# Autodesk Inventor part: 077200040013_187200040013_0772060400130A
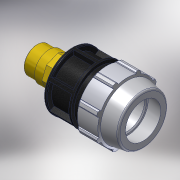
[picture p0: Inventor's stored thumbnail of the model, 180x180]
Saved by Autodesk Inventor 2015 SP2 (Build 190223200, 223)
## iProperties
Created: 2017-02
Part Number: 077200040013_187200040013_0772060400130A
Material: PVC-Piping
Description: PLASSON MALE ADAPTOR INTEGRAL BRASS THREAD 40-1.1/4"
Document SubType Name: Modeling
Designer: KIM
Mass: 92.6774 g
Surface Area: 199.44 cm^2
Volume: 66.1981 cm^3
Density: 1.4 g/cm^3
Appearance: PTFE
Author: KIM
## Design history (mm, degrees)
derived "07720.ipt"
feature "Solid1::07720.ipt"
tag "TaggingFeature1"
body "Solid1"
other parameters: "d4" = 22, "d5" = 22, "d7" = 82, "d8" = 61.5, "d9" = 22, "d11" = 4.4, "d12" = 65.6, "d13" = 120 deg, "d15" = 10 deg, "d16" = 73.8, "d18" = 2, "d19" = 35 deg, "d20" = 17.5 deg, "d21" = 76.26, "d23" = 0, "d25" = 360 deg, "d27" = 1.64, "d34" = 4.1, "d36" = 0, "d42" = 30.8, "d43" = 2.46, "d46" = 1.2, "d49" = 91, "d51" = 154, "d53" = 0.8, "d55" = 360 deg, "d59" = 30.8, "d60" = 41.91, "d61" = 46.101, "d62" = 22, "d63" = 51.33333, "d64" = 29.337, "d65" = 154, "d66" = 16.1482, "d67" = 0, "d68" = 0.8, "d71" = 30 deg, "d72" = 37.719, "E_" = 82, "H_" = 154, "l_" = 91, "l_2" = 22, "R_" = 41.91, "d73" = 26.91366
